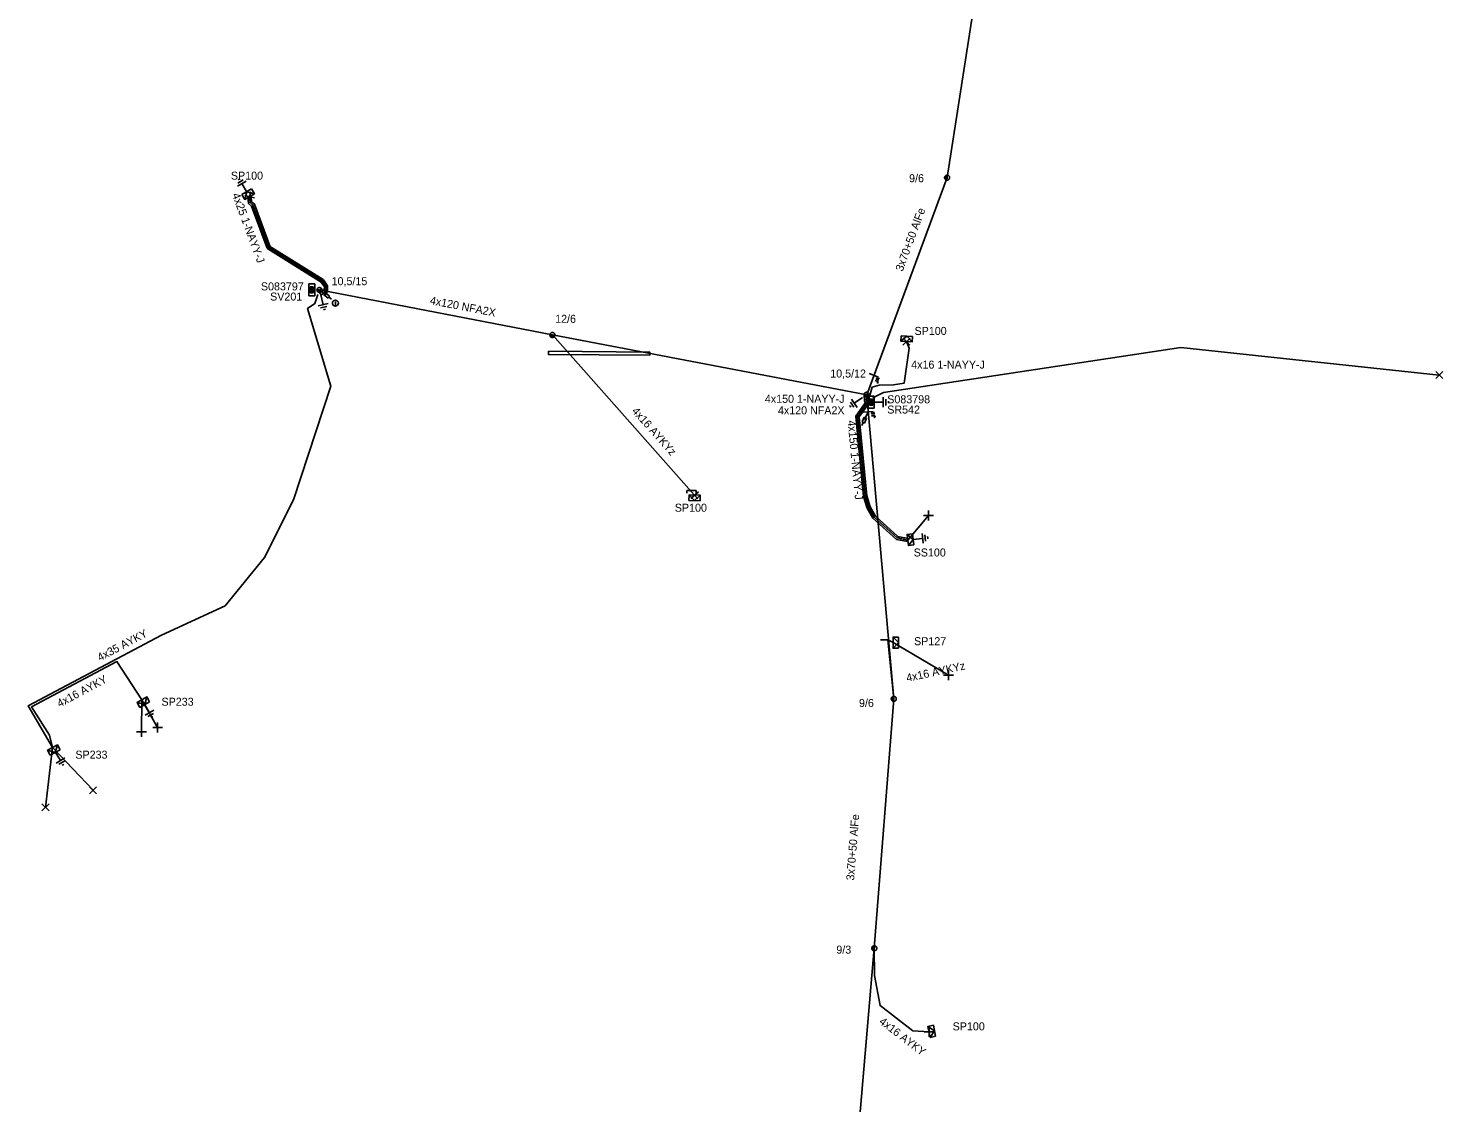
# Model space of a CAD drawing. Extents: x -717562 to -713845, y -1151196 to -1143903.
# Drawn here: x -714219.8 to -714043.1, y -1146983.8 to -1146849.6 of the extents above; entities that cross this region are included whole.
import ezdxf

# ---------------------------------------------------------------- set-up
doc = ezdxf.new("R2010")
doc.units = 0
for name, color, linetype in [('Vrstva 1', 7, 'Continuous'), ('Vrstva 10', 7, 'Continuous'), ('Vrstva 12', 7, 'Continuous'), ('Vrstva 13', 7, 'Continuous'), ('Vrstva 14', 7, 'Continuous'), ('Vrstva 15', 7, 'Continuous'), ('Vrstva 16', 7, 'Continuous'), ('Vrstva 18', 7, 'Continuous'), ('Vrstva 2', 7, 'Continuous'), ('Vrstva 20', 7, 'Continuous'), ('Vrstva 28', 7, 'Continuous'), ('Vrstva 29', 7, 'Continuous'), ('Vrstva 30', 7, 'Continuous'), ('Vrstva 31', 7, 'Continuous'), ('Vrstva 33', 7, 'Continuous'), ('Vrstva 34', 7, 'Continuous'), ('Vrstva 36', 7, 'Continuous'), ('Vrstva 5', 7, 'Continuous'), ('Vrstva 50', 7, 'Continuous'), ('Vrstva 51', 7, 'Continuous'), ('Vrstva 52', 7, 'Continuous'), ('Vrstva 54', 7, 'Continuous'), ('Vrstva 55', 7, 'Continuous'), ('Vrstva 59', 7, 'Continuous'), ('Vrstva 6', 7, 'Continuous'), ('Vrstva 8', 7, 'Continuous'), ('Vrstva 9', 7, 'Continuous')]:
    doc.layers.add(name, color=color, linetype=linetype)

# ---------------------------------------------------------------- blocks, each defined once
blk = doc.blocks.new('NN440')
at = {"layer": 'Vrstva 2'}
for points in [[(0.63, 0), (0.63, 0.06), (0.62, 0.13), (0.6, 0.19), (0.58, 0.25), (0.55, 0.31), (0.51, 0.37), (0.47, 0.42), (0.42, 0.46), (0.37, 0.51), (0.32, 0.54), (0.26, 0.57), (0.2, 0.59), (0.13, 0.61), (0.07, 0.62), (0, 0.63), (-0.06, 0.62), (-0.13, 0.61), (-0.19, 0.59), (-0.26, 0.57), (-0.31, 0.54), (-0.37, 0.51), (-0.42, 0.46), (-0.47, 0.42), (-0.51, 0.37), (-0.54, 0.31), (-0.57, 0.25), (-0.6, 0.19), (-0.62, 0.13), (-0.63, 0.06), (-0.63, 0), (-0.63, -0.07), (-0.62, -0.14), (-0.6, -0.2), (-0.57, -0.26), (-0.54, -0.32), (-0.51, -0.37), (-0.47, -0.43), (-0.42, -0.47), (-0.37, -0.51), (-0.31, -0.55), (-0.26, -0.58), (-0.19, -0.6), (-0.13, -0.62), (-0.06, -0.63), (0, -0.63), (0.07, -0.63), (0.13, -0.62), (0.2, -0.6), (0.26, -0.58), (0.32, -0.55), (0.37, -0.51), (0.42, -0.47), (0.47, -0.43), (0.51, -0.37), (0.55, -0.32), (0.58, -0.26), (0.6, -0.2), (0.62, -0.14), (0.63, -0.07), (0.63, 0)], [(-0.63, 0), (0.63, 0)], [(-0.6, -0.18), (0.57, -0.18)], [(-0.51, -0.32), (0.5, -0.32)], [(-0.37, -0.47), (0.35, -0.47)]]:
    blk.add_lwpolyline(points, dxfattribs=at)
blk = doc.blocks.new('NN840')
at = {"layer": 'Vrstva 15'}
for points in [[(0, 0.62), (0, -0.63)], [(-0.75, -0.71), (-0.75, -0.66)], [(-0.73, -0.76), (-0.75, -0.71)], [(-0.66, -0.8), (-0.73, -0.76)], [(-0.63, -0.8), (-0.66, -0.8)], [(-0.56, -0.76), (-0.63, -0.8)], [(-0.54, -0.71), (-0.56, -0.76)], [(-0.54, -0.38), (-0.54, -0.71)], [(-0.33, -0.38), (-0.33, -0.8)], [(-0.33, -0.64), (-0.13, -0.38)], [(-0.26, -0.56), (-0.09, -0.8)]]:
    blk.add_lwpolyline(points, dxfattribs=at)
blk = doc.blocks.new('NN770')
at = {"layer": 'Vrstva 10'}
for p, q in [((0, 0.19), (0, 0.26)), ((0, -0.28), (0, 0.11))]:
    blk.add_line(p, q, dxfattribs=at)
blk.add_circle((0, -0.01), 0.375, dxfattribs=at)
blk = doc.blocks.new('NN800')
at = {"layer": 'Vrstva 1'}
for points in [[(-0.44, 0.44), (0.44, -0.44)], [(-0.44, -0.44), (0.44, 0.44)]]:
    blk.add_lwpolyline(points, dxfattribs=at)
blk = doc.blocks.new('NN820')
at = {"layer": 'Vrstva 13'}
for points in [[(0, 0), (0, -1.05)], [(-0.16, -0.81), (0.16, -0.81)], [(-0.16, -1.47), (-0.16, -0.81)], [(0.16, -1.47), (-0.16, -1.47)], [(0, -1.05), (-0.06, -0.93)], [(0, -1.05), (0.06, -0.93)], [(0, -1.47), (0, -1.87)], [(0.16, -0.81), (0.16, -1.47)]]:
    blk.add_lwpolyline(points, dxfattribs=at)
blk = doc.blocks.new('NN620')
at = {"layer": 'Vrstva 8'}
for points in [[(0.75, 0), (-0.75, 0)], [(-0.75, 0), (-0.75, -0.75)], [(0.75, -0.75), (0.75, 0)], [(-0.75, -0.75), (0.75, -0.75)], [(0.37, -0.18), (-0.38, -0.18)], [(-0.38, -0.18), (-0.38, -0.56)], [(-0.38, -0.56), (0.37, -0.56)], [(0.32, -0.23), (-0.33, -0.23)], [(-0.33, -0.23), (-0.33, -0.51)], [(-0.33, -0.51), (0.32, -0.51)], [(0.27, -0.27), (-0.28, -0.27)], [(-0.28, -0.27), (-0.28, -0.46)], [(-0.28, -0.46), (0.27, -0.46)], [(0.23, -0.32), (-0.23, -0.32)], [(-0.23, -0.32), (-0.23, -0.42)], [(-0.23, -0.42), (0.23, -0.42)], [(-0.19, -0.37), (0.19, -0.37)], [(0.23, -0.42), (0.23, -0.32)], [(0.27, -0.46), (0.27, -0.27)], [(0.32, -0.51), (0.32, -0.23)], [(0.37, -0.56), (0.37, -0.18)]]:
    blk.add_lwpolyline(points, dxfattribs=at)
blk = doc.blocks.new('NN630')
at = {"layer": 'Vrstva 9'}
for points in [[(0, -0.7), (-0.7, 0)], [(-0.7, -0.7), (-0.7, 0), (0.7, 0), (0.7, -0.7)], [(-0.7, -0.7), (0.7, -0.7)], [(0, -0.7), (0.7, 0)]]:
    blk.add_lwpolyline(points, dxfattribs=at)
blk = doc.blocks.new('NN810')
at = {"layer": 'Vrstva 14'}
for points in [[(0, -0.64), (0, -1.89)], [(0.63, -1.89), (-0.62, -1.89)], [(0.39, -2.2), (-0.4, -2.2)], [(0, -2.52), (-0.12, -2.52)], [(0.14, -2.52), (0, -2.52)]]:
    blk.add_lwpolyline(points, dxfattribs=at)
blk = doc.blocks.new('NN510')
at = {"layer": 'Vrstva 2'}
blk.add_lwpolyline([(0, 0), (0, 0.94)], dxfattribs=at)
blk = doc.blocks.new('NN515')
at = {"layer": 'Vrstva 2'}
for points in [[(-0.59, 0.18), (0.59, 0.18)], [(-0.59, 0.18), (-0.59, -0.18)], [(0.59, 0.18), (0.59, -0.18)]]:
    blk.add_lwpolyline(points, dxfattribs=at)

msp = doc.modelspace()

# ---------------------------------------------------------------- linework, layer by layer
at = {"layer": 'Vrstva 1'}
for points in [[(-714115.04, -1146895.35), (-714105, -1146868.24), (-714101.3, -1146844.64), (-714093.62, -1146824.06)], [(-714118.86, -1147032.12), (-714116.8, -1146996.15), (-714114.09, -1146964.48), (-714111.65, -1146933.33), (-714114.99, -1146895.94)]]:
    msp.add_lwpolyline(points, dxfattribs=at)
at = {"layer": 'Vrstva 20'}
for points in [[(-714189.94, -1146877.03), (-714191.88, -1146871.79), (-714192.26, -1146871.46), (-714192.34, -1146870.63), (-714191.94, -1146870.59), (-714191.88, -1146871.26), (-714191.54, -1146871.55), (-714189.56, -1146876.89)], [(-714189.64, -1146876.79), (-714182.96, -1146880.95), (-714183.18, -1146881.29), (-714189.86, -1146877.13)], [(-714183.24, -1146882.15), (-714183.08, -1146882.36), (-714182.8, -1146882.24), (-714182.78, -1146881.86), (-714183.23, -1146881.24), (-714182.91, -1146881), (-714182.38, -1146881.74), (-714182.4, -1146882.5), (-714183.2, -1146882.86), (-714183.56, -1146882.39)], [(-714154.77, -1146889.93), (-714142.14, -1146890.02), (-714142.14, -1146890.42), (-714154.77, -1146890.33)], [(-714114.74, -1146895.34), (-714114.72, -1146895.94), (-714114.61, -1146896.11), (-714115.09, -1146896.45), (-714115.32, -1146896.14), (-714115.34, -1146895.36)], [(-714109.95, -1146913.7), (-714111.32, -1146913.42), (-714114.27, -1146910.78), (-714114.96, -1146909.52), (-714115.44, -1146908.06), (-714116.01, -1146902.01), (-714116.39, -1146898.03), (-714115.23, -1146896.38), (-714114.91, -1146896.6), (-714115.97, -1146898.13), (-714115.61, -1146901.97), (-714115.04, -1146907.98), (-714114.6, -1146909.36), (-714113.95, -1146910.52), (-714111.14, -1146913.04), (-714109.87, -1146913.3)]]:
    msp.add_lwpolyline(points, close=True, dxfattribs=at)
at = {"layer": 'Vrstva 5'}
for points in [[(-714183.6, -1146882.85), (-714183.97, -1146883.96), (-714184.89, -1146884.57), (-714182, -1146894.28), (-714186.63, -1146908.46), (-714190.28, -1146915.69), (-714195.19, -1146921.72), (-714203.12, -1146925.37), (-714219.78, -1146934.2), (-714216.76, -1146939.42)], [(-714114.85, -1146896.28), (-714115.12, -1146896.07), (-714115.04, -1146895.35)], [(-714114.84, -1146896.06), (-714114.99, -1146895.94)], [(-714114.85, -1146896.46), (-714115.07, -1146896.49), (-714116.18, -1146898.08), (-714115.81, -1146901.99), (-714115.24, -1146908.02), (-714114.78, -1146909.44), (-714114.11, -1146910.65), (-714111.23, -1146913.23), (-714109.91, -1146913.5)]]:
    msp.add_lwpolyline(points, dxfattribs=at)
at = {"layer": 'Vrstva 50'}
msp.add_lwpolyline([(-714115.04, -1146895.35), (-714154.3, -1146887.89), (-714183.4, -1146882.27)], dxfattribs=at)
at = {"layer": 'Vrstva 52'}
for points in [[(-714182.87, -1146882.49), (-714182.6, -1146882.37), (-714182.58, -1146881.8), (-714183.07, -1146881.12), (-714189.75, -1146876.96), (-714191.71, -1146871.67), (-714192.07, -1146871.36), (-714192.14, -1146870.61)], [(-714114.7, -1146895.63), (-714114.62, -1146895.26), (-714114.34, -1146894.39), (-714113.47, -1146894.14), (-714111.67, -1146894.13), (-714110.35, -1146893.9), (-714109.74, -1146889.55), (-714110.06, -1146888.72)], [(-714216.76, -1146939.42), (-714217.13, -1146937.86), (-714219.36, -1146934.34), (-714208.71, -1146928.67), (-714205.58, -1146933.44)], [(-714114.09, -1146964.48), (-714114.08, -1146967.89), (-714113.37, -1146971.64), (-714109.28, -1146974.77), (-714107.25, -1146974.92)]]:
    msp.add_lwpolyline(points, dxfattribs=at)
at = {"layer": 'Vrstva 54'}
for points in [[(-714154.3, -1146887.89), (-714136.92, -1146907.48), (-714136.53, -1146907.88)], [(-714111.65, -1146933.33), (-714112.38, -1146925.95), (-714111.75, -1146926.31)]]:
    msp.add_lwpolyline(points, dxfattribs=at)
at = {"layer": 'Vrstva 59'}
for points in [[(-714114.25, -1146895.73), (-714112.94, -1146895.08), (-714075.78, -1146889.46), (-714043.51, -1146892.89)], [(-714109.91, -1146913.5), (-714107.33, -1146910.45)], [(-714111.75, -1146926.31), (-714104.81, -1146930.38)], [(-714205.58, -1146933.44), (-714205.63, -1146937.44)], [(-714205.58, -1146933.44), (-714203.62, -1146936.92)], [(-714216.76, -1146939.42), (-714217.63, -1146946.88)], [(-714216.76, -1146939.42), (-714211.69, -1146944.75)]]:
    msp.add_lwpolyline(points, dxfattribs=at)

# ---------------------------------------------------------------- block references
at = {"layer": 'Vrstva 13'}
for p, xscale, yscale, rotation in [((-714104.99, -1146868.24), 0.5, 0.5, -99.944152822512), ((-714183.4, -1146882.27), 0.5, 0.5000000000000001, -10.9307969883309), ((-714154.3, -1146887.89), 0.5, 0.5000000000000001, -10.75881218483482), ((-714115.04, -1146895.35), 0.49999999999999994, 0.49999999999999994, -10.758812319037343), ((-714111.65, -1146933.33), 0.49999999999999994, 0.5000000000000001, -93.58155283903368), ((-714114.09, -1146964.48), 0.49999999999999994, 0.5000000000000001, -93.29178337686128)]:
    msp.add_blockref('NN440', p, dxfattribs=dict(at, xscale=xscale, yscale=yscale, rotation=rotation))
msp.add_blockref('NN515', (-714136.92, -1146907.48), dxfattribs=at)
at = {"layer": 'Vrstva 13', "rotation": 90}
msp.add_blockref('NN510', (-714112.38, -1146925.95), dxfattribs=at)
at = {"layer": 'Vrstva 15'}
for p, rotation in [((-714192.14, -1146870.61), -149.34933626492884), ((-714183.4, -1146882.27), 13.855180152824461), ((-714115.04, -1146895.35), -55.45908285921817), ((-714114.85, -1146896.28), 90.00000109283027), ((-714109.91, -1146913.5), 96.49934786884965), ((-714205.6, -1146933.44), 30.249777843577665), ((-714216.76, -1146939.42), 31.484977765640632)]:
    msp.add_blockref('NN810', p, dxfattribs=dict(at, rotation=rotation))
at = {"layer": 'Vrstva 16'}
for p, rotation in [((-714183.4, -1146882.27), 52.87235388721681), ((-714114.85, -1146897.49), -25.13104443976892)]:
    msp.add_blockref('NN820', p, dxfattribs=dict(at, rotation=rotation))
at = {"layer": 'Vrstva 18'}
for p, rotation in [((-714114.14, -1146892.93), 69.6689534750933), ((-714114.85, -1146897.49), 95.10055846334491)]:
    msp.add_blockref('NN840', p, dxfattribs=dict(at, rotation=rotation))
at = {"layer": 'Vrstva 28'}
for p, rotation in [((-714184, -1146882.25), -90), ((-714114.85, -1146896.28), 90.00000109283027)]:
    msp.add_blockref('NN620', p, dxfattribs=dict(at, rotation=rotation))
at = {"layer": 'Vrstva 31'}
for p, rotation in [((-714192.14, -1146870.61), -149.34933626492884), ((-714110.06, -1146888.72), 176.76901608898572), ((-714136.53, -1146907.88), -2.0095722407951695), ((-714109.91, -1146913.5), 96.49934786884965), ((-714111.75, -1146926.31), 90), ((-714205.58, -1146933.44), 29.266458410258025), ((-714216.76, -1146939.42), 28.701783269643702), ((-714107.25, -1146974.92), 101.83585282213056)]:
    msp.add_blockref('NN630', p, dxfattribs=dict(at, rotation=rotation))
at = {"layer": 'Vrstva 34'}
for p, rotation in [((-714192.14, -1146870.61), 30.650663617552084), ((-714110.06, -1146888.72), -2.05982043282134), ((-714136.53, -1146907.88), -2.846302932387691), ((-714107.33, -1146910.45), 45), ((-714104.81, -1146930.38), 45), ((-714203.62, -1146936.92), 44.99999995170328), ((-714205.63, -1146937.44), 45), ((-714107.25, -1146974.92), 44.99999995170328)]:
    msp.add_blockref('NN800', p, dxfattribs=dict(at, rotation=rotation))
for p in [(-714043.51, -1146892.89), (-714211.69, -1146944.75), (-714217.63, -1146946.88)]:
    msp.add_blockref('NN800', p, dxfattribs=at)
at = {"layer": 'Vrstva 36'}
msp.add_blockref('NN770', (-714181.42, -1146883.9), dxfattribs=at)

# ---------------------------------------------------------------- texts
at = {"layer": 'Vrstva 12'}
for s, p in [('9/6', (-714109.74, -1146868.81)), ('10,5/15', (-714181.89, -1146881.67)), ('12/6', (-714153.96, -1146886.37)), ('10,5/12', (-714119.59, -1146893.2)), ('9/6', (-714116, -1146934.35)), ('9/3', (-714118.83, -1146965.15))]:
    msp.add_text(s, height=1, dxfattribs=at).set_placement(p)
at = {"layer": 'Vrstva 2'}
for rotation, p in [(69.796, (-714110.55, -1146880.02)), (85.522, (-714116.61, -1146956.04))]:
    msp.add_text('3x70+50 AlFe', height=1, rotation=rotation, dxfattribs=at).set_placement(p)
at = {"layer": 'Vrstva 29'}
for s, p in [('S083797', (-714190.72, -1146882.32)), ('S083798', (-714112.47, -1146896.42))]:
    msp.add_text(s, height=1, dxfattribs=at).set_placement(p)
at = {"layer": 'Vrstva 30'}
for s, p in [('SV201', (-714189.57, -1146883.59)), ('SR542', (-714112.47, -1146897.7))]:
    msp.add_text(s, height=1, dxfattribs=at).set_placement(p)
at = {"layer": 'Vrstva 33'}
for s, p in [('SP100', (-714194.47, -1146868.49)), ('SP100', (-714109.06, -1146887.88)), ('SP100', (-714139.01, -1146909.96)), ('SS100', (-714109.17, -1146915.55)), ('SP127', (-714109.12, -1146926.63)), ('SP233', (-714203.14, -1146934.19)), ('SP233', (-714213.9, -1146940.8)), ('SP100', (-714104.3, -1146974.73))]:
    msp.add_text(s, height=1, dxfattribs=at).set_placement(p)
at = {"layer": 'Vrstva 51'}
msp.add_text('4x120 NFA2X', height=1, rotation=349.069, dxfattribs=at).set_placement((-714169.66, -1146884.02))
at = {"layer": 'Vrstva 54'}
for s, rotation, p in [('4x25 1-NAYY-J', 290.33, (-714194.34, -1146870.36)), ('4x16 AYKY', 28.003, (-714215.87, -1146934.42)), ('4x16 AYKY', 322.608, (-714113.57, -1146973.81))]:
    msp.add_text(s, height=1, rotation=rotation, dxfattribs=at).set_placement(p)
msp.add_text('4x16 1-NAYY-J', height=1, dxfattribs=at).set_placement((-714109.48, -1146892.09))
at = {"layer": 'Vrstva 55'}
for rotation, p in [(311.579, (-714144.45, -1146897.44)), (12.18, (-714109.98, -1146931.22))]:
    msp.add_text('4x16 AYKYz', height=1, rotation=rotation, dxfattribs=at).set_placement(p)
at = {"layer": 'Vrstva 6'}
for s, p in [('4x150 1-NAYY-J', (-714127.76, -1146896.36)), ('4x120 NFA2X', (-714126.13, -1146897.8))]:
    msp.add_text(s, height=1, dxfattribs=at).set_placement(p)
for s, rotation, p in [('4x150 1-NAYY-J', 275.4, (-714117.43, -1146898.59)), ('4x35 AYKY', 27.916, (-714210.84, -1146928.67))]:
    msp.add_text(s, height=1, rotation=rotation, dxfattribs=at).set_placement(p)

doc.saveas('drawing.dxf')
